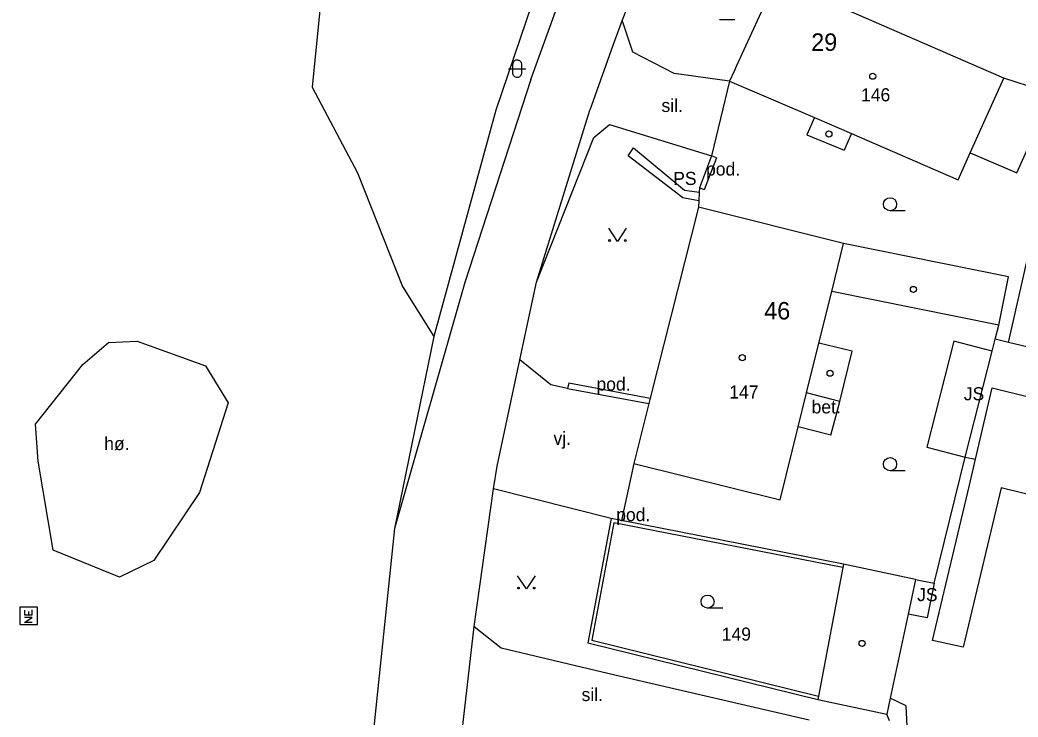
# Model space of a CAD drawing. Extents: x -836739 to -835945, y -1070775 to -1070126.
# Drawn here: x -836678.6 to -836621.5, y -1070479.9 to -1070440 of the extents above; entities that cross this region are included whole.
import ezdxf

# ---------------------------------------------------------------- set-up
doc = ezdxf.new("R2010")
doc.units = 0
for name, color, linetype in [('BodPole_mer', 7, 'Continuous'), ('Budovy_hranice', 7, 'Continuous'), ('Budovy_kody', 7, 'Continuous'), ('Doprava_hranice', 7, 'Continuous'), ('Doprava_kody', 7, 'Continuous'), ('OstPloch_hranice', 7, 'Continuous'), ('OstPloch_kody', 7, 'Continuous'), ('PovrZnIS_body', 7, 'Continuous'), ('RuianAdr_popis', 7, 'Continuous'), ('RuianPar_popis', 7, 'Continuous'), ('Stavby_hr_stav', 7, 'Continuous'), ('Stavby_kody', 7, 'Continuous'), ('Stavby_linie', 7, 'Continuous'), ('Zelen_kody', 7, 'Continuous')]:
    doc.layers.add(name, color=color, linetype=linetype)

msp = doc.modelspace()

# ---------------------------------------------------------------- linework, layer by layer
at = {"layer": 'BodPole_mer'}
for p, q in [((-836644.12, -1070440), (-836644.12, -1070440)), ((-836644.66, -1070441.44), (-836644.66, -1070441.44)), ((-836643.52, -1070441.83), (-836643.52, -1070441.83)), ((-836637.7, -1070442.88), (-836637.7, -1070442.88)), ((-836637.6, -1070442.65), (-836637.6, -1070442.65)), ((-836649.35, -1070443.39), (-836649.35, -1070443.39)), ((-836641.15, -1070443.05), (-836641.15, -1070443.05)), ((-836637.98, -1070443.48), (-836637.98, -1070443.48)), ((-836622.29, -1070443.32), (-836622.29, -1070443.32)), ((-836661.86, -1070443.82), (-836661.86, -1070443.82)), ((-836651.36, -1070445.15), (-836651.36, -1070445.15)), ((-836645.98, -1070445.15), (-836645.98, -1070445.15)), ((-836633.13, -1070445.57), (-836633.13, -1070445.57)), ((-836644.85, -1070445.96), (-836644.85, -1070445.96)), ((-836645.75, -1070446.71), (-836645.75, -1070446.71)), ((-836633.56, -1070446.56), (-836633.56, -1070446.56)), ((-836631.01, -1070446.49), (-836631.01, -1070446.49)), ((-836643.48, -1070447.3), (-836643.48, -1070447.3)), ((-836631.42, -1070447.44), (-836631.42, -1070447.44)), ((-836624.21, -1070447.58), (-836624.21, -1070447.58)), ((-836643.78, -1070447.76), (-836643.78, -1070447.76)), ((-836639.01, -1070447.76), (-836639.01, -1070447.76)), ((-836638.73, -1070447.87), (-836638.73, -1070447.87)), ((-836659.27, -1070448.73), (-836659.27, -1070448.73)), ((-836621.54, -1070448.73), (-836621.54, -1070448.73)), ((-836624.91, -1070449.13), (-836624.91, -1070449.13)), ((-836640.56, -1070449.72), (-836640.56, -1070449.72)), ((-836639.72, -1070449.85), (-836639.72, -1070449.85)), ((-836639.71, -1070449.6), (-836639.71, -1070449.6)), ((-836639.43, -1070449.71), (-836639.43, -1070449.71)), ((-836640.65, -1070450.17), (-836640.65, -1070450.17)), ((-836639.74, -1070450.33), (-836639.74, -1070450.33)), ((-836639.76, -1070450.7), (-836639.76, -1070450.7)), ((-836631.47, -1070452.78), (-836631.47, -1070452.78)), ((-836653.14, -1070455.02), (-836653.14, -1070455.02)), ((-836649.04, -1070455), (-836649.04, -1070455)), ((-836622.02, -1070454.69), (-836622.02, -1070454.69)), ((-836656.69, -1070455.24), (-836656.69, -1070455.24)), ((-836632.14, -1070455.52), (-836632.14, -1070455.52)), ((-836622.58, -1070457.45), (-836622.58, -1070457.45)), ((-836673.53, -1070458.44), (-836673.53, -1070458.44)), ((-836671.89, -1070458.38), (-836671.89, -1070458.38)), ((-836654.9, -1070458.11), (-836654.9, -1070458.11)), ((-836625.15, -1070458.38), (-836625.15, -1070458.38)), ((-836622.78, -1070458.25), (-836622.78, -1070458.25)), ((-836622.02, -1070458.45), (-836622.02, -1070458.45)), ((-836632.88, -1070458.48), (-836632.88, -1070458.48)), ((-836630.97, -1070458.95), (-836630.97, -1070458.95)), ((-836622.96, -1070458.94), (-836622.96, -1070458.94)), ((-836649.99, -1070459.44), (-836649.99, -1070459.44)), ((-836674.99, -1070459.71), (-836674.99, -1070459.71)), ((-836667.97, -1070459.78), (-836667.97, -1070459.78)), ((-836648.21, -1070460.88), (-836648.21, -1070460.88)), ((-836647.25, -1070461.08), (-836647.25, -1070461.08)), ((-836647.19, -1070460.76), (-836647.19, -1070460.76)), ((-836622.96, -1070461.05), (-836622.96, -1070461.05)), ((-836642.52, -1070461.63), (-836642.52, -1070461.63)), ((-836633.58, -1070461.34), (-836633.58, -1070461.34)), ((-836631.68, -1070461.82), (-836631.68, -1070461.82)), ((-836666.68, -1070461.9), (-836666.68, -1070461.9)), ((-836642.61, -1070461.95), (-836642.61, -1070461.95)), ((-836677.71, -1070463.13), (-836677.71, -1070463.13)), ((-836634.06, -1070463.28), (-836634.06, -1070463.28)), ((-836632.19, -1070463.75), (-836632.19, -1070463.75)), ((-836626.69, -1070464.45), (-836626.69, -1070464.45)), ((-836677.54, -1070465.24), (-836677.54, -1070465.24)), ((-836624.5, -1070465.01), (-836624.5, -1070465.01)), ((-836623.9, -1070465.13), (-836623.9, -1070465.13)), ((-836651.28, -1070465.53), (-836651.28, -1070465.53)), ((-836643.47, -1070465.37), (-836643.47, -1070465.37)), ((-836651.49, -1070466.82), (-836651.49, -1070466.82)), ((-836624.25, -1070466.62), (-836624.25, -1070466.62)), ((-836622.44, -1070466.77), (-836622.44, -1070466.77)), ((-836668.32, -1070467.04), (-836668.32, -1070467.04)), ((-836635.09, -1070467.46), (-836635.09, -1070467.46)), ((-836644.76, -1070468.53), (-836644.76, -1070468.53)), ((-836644.16, -1070468.65), (-836644.16, -1070468.65)), ((-836657.15, -1070469.1), (-836657.15, -1070469.1)), ((-836644.6, -1070468.77), (-836644.6, -1070468.77)), ((-836676.69, -1070470.34), (-836676.69, -1070470.34)), ((-836670.93, -1070470.93), (-836670.93, -1070470.93)), ((-836631.5, -1070471.34), (-836631.5, -1070471.34)), ((-836631.46, -1070471.15), (-836631.46, -1070471.15)), ((-836672.9, -1070471.89), (-836672.9, -1070471.89)), ((-836627.35, -1070472.02), (-836627.35, -1070472.02)), ((-836626.28, -1070472.23), (-836626.28, -1070472.23)), ((-836678.09, -1070474.1), (-836678.09, -1070474.1)), ((-836627.77, -1070474), (-836627.77, -1070474)), ((-836626.68, -1070474.21), (-836626.68, -1070474.21)), ((-836652.59, -1070474.71), (-836652.59, -1070474.71)), ((-836645.86, -1070475.49), (-836645.86, -1070475.49)), ((-836626.37, -1070475.52), (-836626.37, -1070475.52)), ((-836651.05, -1070475.93), (-836651.05, -1070475.93)), ((-836646.09, -1070475.64), (-836646.09, -1070475.64)), ((-836624.62, -1070475.89), (-836624.62, -1070475.89)), ((-836644.54, -1070477.48), (-836644.54, -1070477.48)), ((-836632.94, -1070478.89), (-836632.94, -1070478.89)), ((-836632.9, -1070478.69), (-836632.9, -1070478.69)), ((-836628.79, -1070478.81), (-836628.79, -1070478.81)), ((-836627.88, -1070479.26), (-836627.88, -1070479.26)), ((-836628.99, -1070479.73), (-836628.99, -1070479.73))]:
    msp.add_line(p, q, dxfattribs=at)
at = {"layer": 'Budovy_hranice'}
for p, q in [((-836622.29, -1070443.32), (-836635.32, -1070437.63)), ((-836616.07, -1070445.32), (-836622.29, -1070443.32)), ((-836633.13, -1070445.57), (-836633.56, -1070446.56)), ((-836633.56, -1070446.56), (-836631.42, -1070447.44)), ((-836631.01, -1070446.49), (-836631.42, -1070447.44)), ((-836621.54, -1070448.73), (-836620.62, -1070446.7)), ((-836624.21, -1070447.58), (-836621.54, -1070448.73)), ((-836622.58, -1070457.45), (-836622.02, -1070454.69)), ((-836622.58, -1070457.45), (-836632.14, -1070455.52)), ((-836630.97, -1070458.95), (-836632.88, -1070458.48)), ((-836631.68, -1070461.82), (-836630.97, -1070458.95)), ((-836631.68, -1070461.82), (-836633.58, -1070461.34)), ((-836643.47, -1070465.37), (-836635.09, -1070467.46)), ((-836627.35, -1070472.02), (-836631.46, -1070471.15)), ((-836632.94, -1070478.89), (-836628.99, -1070479.73))]:
    msp.add_line(p, q, dxfattribs=at)
for points in [[(-836635.32, -1070437.63), (-836635.42, -1070437.86), (-836637.6, -1070442.65), (-836637.7, -1070442.88), (-836637.98, -1070443.48)], [(-836637.98, -1070443.48), (-836633.13, -1070445.57), (-836631.01, -1070446.49), (-836624.91, -1070449.13)], [(-836624.91, -1070449.13), (-836624.21, -1070447.58), (-836622.29, -1070443.32)], [(-836616.17, -1070459.86), (-836616.95, -1070459.66), (-836622.02, -1070458.45), (-836620.76, -1070452.9), (-836617.02, -1070453.79), (-836616.09, -1070450.28), (-836613.73, -1070450.82)], [(-836639.76, -1070450.7), (-836642.52, -1070461.63), (-836642.61, -1070461.95), (-836643.47, -1070465.37)], [(-836622.02, -1070454.69), (-836631.47, -1070452.78), (-836639.76, -1070450.7)], [(-836635.09, -1070467.46), (-836634.06, -1070463.28), (-836633.58, -1070461.34), (-836632.88, -1070458.48), (-836632.14, -1070455.52), (-836631.47, -1070452.78)], [(-836631.46, -1070471.15), (-836631.5, -1070471.34), (-836632.9, -1070478.69), (-836632.94, -1070478.89)], [(-836627.35, -1070472.02), (-836627.77, -1070474), (-836628.79, -1070478.81), (-836628.99, -1070479.73)]]:
    msp.add_lwpolyline(points, dxfattribs=at)
at = {"layer": 'Budovy_kody'}
for centre in [(-836629.79, -1070443.2), (-836632.3, -1070446.51), (-836627.46, -1070455.41), (-836637.26, -1070459.32), (-836632.23, -1070460.21), (-836630.4, -1070475.68)]:
    msp.add_circle(centre, 0.175, dxfattribs=at)
at = {"layer": 'Doprava_hranice'}
for p, q in [((-836649.35, -1070443.39), (-836653.14, -1070455.02)), ((-836649.04, -1070455), (-836645.98, -1070445.15)), ((-836653.14, -1070455.02), (-836657.15, -1070469.1)), ((-836644.76, -1070468.53), (-836651.49, -1070466.82)), ((-836657.15, -1070469.1), (-836658.42, -1070481.32)), ((-836653.53, -1070482.71), (-836652.59, -1070474.71)), ((-836652.59, -1070474.71), (-836651.05, -1070475.93)), ((-836651.05, -1070475.93), (-836644.54, -1070477.48)), ((-836644.54, -1070477.48), (-836633.42, -1070480.06)), ((-836628.84, -1070480.11), (-836628.99, -1070479.73))]:
    msp.add_line(p, q, dxfattribs=at)
for points in [[(-836629.46, -1070381.04), (-836630.1, -1070382.38), (-836632.83, -1070381.55), (-836636.09, -1070386.19), (-836641.48, -1070386.97), (-836650.79, -1070382.45), (-836653.8, -1070405.82), (-836653.8, -1070413.64), (-836660.69, -1070431.93), (-836661.86, -1070443.82), (-836659.27, -1070448.73), (-836656.69, -1070455.24), (-836654.9, -1070458.11)], [(-836626.49, -1070382.25), (-836628.93, -1070385.76), (-836634.87, -1070398.93), (-836637.79, -1070403.09), (-836640.55, -1070405.67), (-836641.83, -1070408.47), (-836641.31, -1070415.5), (-836651.36, -1070445.15), (-836654.9, -1070458.11), (-836657.15, -1070469.1)], [(-836649.35, -1070443.39), (-836643.96, -1070428.49), (-836637.13, -1070410.36)], [(-836636.57, -1070420.39), (-836639.98, -1070429.29), (-836642.32, -1070435.38), (-836644.12, -1070440), (-836644.66, -1070441.44), (-836645.98, -1070445.15)], [(-836637.98, -1070443.48), (-836641.15, -1070443.05), (-836643.52, -1070441.83), (-836644.12, -1070440)], [(-836649.04, -1070455), (-836645.75, -1070446.71), (-836644.85, -1070445.96), (-836639.01, -1070447.76)], [(-836651.28, -1070465.53), (-836649.99, -1070459.44), (-836649.04, -1070455)], [(-836647.25, -1070461.08), (-836648.21, -1070460.88), (-836649.99, -1070459.44)], [(-836652.59, -1070474.71), (-836651.49, -1070466.82), (-836651.28, -1070465.53)]]:
    msp.add_lwpolyline(points, dxfattribs=at)
at = {"layer": 'OstPloch_hranice'}
msp.add_line((-836624.5, -1070465.01), (-836623.9, -1070465.13), dxfattribs=at)
msp.add_lwpolyline([(-836670.93, -1070470.93), (-836672.9, -1070471.89), (-836676.69, -1070470.34), (-836677.54, -1070465.24), (-836677.71, -1070463.13), (-836674.99, -1070459.71), (-836673.53, -1070458.44), (-836671.89, -1070458.38), (-836667.97, -1070459.78), (-836666.68, -1070461.9), (-836668.32, -1070467.04), (-836670.93, -1070470.93)], dxfattribs=at)
at = {"layer": 'OstPloch_kody'}
for p, q in [((-836637.675, -1070439.98), (-836638.55, -1070439.98)), ((-836650.64, -1070442.77), (-836649.64, -1070442.77)), ((-836650.39, -1070443.02), (-836650.39, -1070442.52)), ((-836649.89, -1070442.52), (-836649.89, -1070443.02)), ((-836627.925, -1070450.91), (-836628.8, -1070450.91)), ((-836627.925, -1070465.79), (-836628.8, -1070465.79)), ((-836638.365, -1070473.66), (-836639.24, -1070473.66))]:
    msp.add_line(p, q, dxfattribs=at)
for points in [[(-836650.14, -1070442.27), (-836650.185, -1070442.274), (-836650.232, -1070442.288), (-836650.277, -1070442.311), (-836650.317, -1070442.343), (-836650.349, -1070442.383), (-836650.372, -1070442.428), (-836650.386, -1070442.475), (-836650.39, -1070442.52)], [(-836650.14, -1070442.27), (-836650.095, -1070442.274), (-836650.048, -1070442.288), (-836650.003, -1070442.311), (-836649.963, -1070442.343), (-836649.931, -1070442.383), (-836649.908, -1070442.428), (-836649.894, -1070442.475), (-836649.89, -1070442.52)], [(-836650.14, -1070443.27), (-836650.185, -1070443.266), (-836650.232, -1070443.252), (-836650.277, -1070443.229), (-836650.317, -1070443.197), (-836650.349, -1070443.157), (-836650.372, -1070443.112), (-836650.386, -1070443.065), (-836650.39, -1070443.02)], [(-836649.89, -1070443.02), (-836649.894, -1070443.065), (-836649.908, -1070443.112), (-836649.931, -1070443.157), (-836649.963, -1070443.197), (-836650.003, -1070443.229), (-836650.048, -1070443.252), (-836650.095, -1070443.266), (-836650.14, -1070443.27)]]:
    msp.add_lwpolyline(points, dxfattribs=at)
for centre in [(-836628.8, -1070450.535), (-836628.8, -1070465.415), (-836639.24, -1070473.285)]:
    msp.add_ellipse(centre, major_axis=(0.375, 0), ratio=0.999999, dxfattribs=at)
at = {"layer": 'PovrZnIS_body'}
for p, q in [((-836677.59, -1070473.6), (-836678.59, -1070473.6)), ((-836678.59, -1070473.6), (-836678.59, -1070474.6)), ((-836677.59, -1070474.6), (-836677.59, -1070473.6)), ((-836678.59, -1070474.6), (-836677.59, -1070474.6))]:
    msp.add_line(p, q, dxfattribs=at)
for points in [[(-836678.333, -1070473.772), (-836678.333, -1070474.035)], [(-836678.108, -1070473.848), (-836678.108, -1070474.035)], [(-836677.883, -1070474.035), (-836677.883, -1070473.754)], [(-836678.333, -1070474.035), (-836677.883, -1070474.035)], [(-836678.333, -1070474.485), (-836677.883, -1070474.201)], [(-836677.883, -1070474.201), (-836678.333, -1070474.201)], [(-836677.883, -1070474.485), (-836678.333, -1070474.485)]]:
    msp.add_lwpolyline(points, dxfattribs=at)
at = {"layer": 'RuianAdr_popis'}
for p, q in [((-836633.31, -1070441.75), (-836633.31, -1070441.75)), ((-836636, -1070457.13), (-836636, -1070457.13))]:
    msp.add_line(p, q, dxfattribs=at)
at = {"layer": 'RuianPar_popis'}
for p, q in [((-836630.46, -1070444.64), (-836630.46, -1070444.64)), ((-836638, -1070461.66), (-836638, -1070461.66)), ((-836638.43, -1070475.52), (-836638.43, -1070475.52))]:
    msp.add_line(p, q, dxfattribs=at)
at = {"layer": 'Stavby_hr_stav'}
for p, q in [((-836639.01, -1070447.76), (-836639.71, -1070449.6)), ((-836638.73, -1070447.87), (-836639.01, -1070447.76)), ((-836639.43, -1070449.71), (-836639.71, -1070449.6)), ((-836647.19, -1070460.76), (-836647.25, -1070461.08)), ((-836647.25, -1070461.08), (-836642.61, -1070461.95)), ((-836632.19, -1070463.75), (-836631.68, -1070461.82)), ((-836632.19, -1070463.75), (-836634.06, -1070463.28))]:
    msp.add_line(p, q, dxfattribs=at)
for points in [[(-836639.74, -1070450.33), (-836640.65, -1070450.17), (-836643.78, -1070447.76), (-836643.48, -1070447.3), (-836640.56, -1070449.72), (-836639.72, -1070449.85)], [(-836626.69, -1070464.45), (-836624.5, -1070465.01), (-836622.96, -1070458.94), (-836625.15, -1070458.38), (-836626.69, -1070464.45)], [(-836626.37, -1070475.52), (-836624.25, -1070466.62), (-836623.9, -1070465.13), (-836622.96, -1070461.05), (-836614.56, -1070463.12), (-836605.88, -1070465.16), (-836606.31, -1070466.85), (-836607.22, -1070470.35), (-836616.08, -1070468.33), (-836622.44, -1070466.77), (-836624.62, -1070475.89), (-836626.37, -1070475.52)], [(-836631.46, -1070471.15), (-836644.16, -1070468.65), (-836644.76, -1070468.53), (-836646.09, -1070475.64), (-836632.94, -1070478.89)], [(-836627.35, -1070472.02), (-836626.28, -1070472.23), (-836626.68, -1070474.21), (-836627.77, -1070474)]]:
    msp.add_lwpolyline(points, dxfattribs=at)
at = {"layer": 'Stavby_linie'}
for p, q in [((-836637.98, -1070443.48), (-836639.01, -1070447.76)), ((-836638.73, -1070447.87), (-836639.43, -1070449.71)), ((-836622.02, -1070458.45), (-836622.78, -1070458.25)), ((-836647.19, -1070460.76), (-836642.52, -1070461.63)), ((-836626.28, -1070472.23), (-836624.5, -1070465.01)), ((-836643.47, -1070465.37), (-836644.16, -1070468.65))]:
    msp.add_line(p, q, dxfattribs=at)
for points in [[(-836639.71, -1070449.6), (-836639.72, -1070449.85), (-836639.74, -1070450.33), (-836639.76, -1070450.7)], [(-836622.96, -1070458.94), (-836622.78, -1070458.25), (-836622.58, -1070457.45)], [(-836631.5, -1070471.34), (-836644.6, -1070468.77), (-836645.86, -1070475.49), (-836632.9, -1070478.69)], [(-836627.77, -1070484.71), (-836627.64, -1070483.88), (-836627.88, -1070479.26), (-836628.79, -1070478.81)]]:
    msp.add_lwpolyline(points, dxfattribs=at)
at = {"layer": 'Zelen_kody'}
for points in [[(-836643.9, -1070451.91), (-836644.4, -1070452.66), (-836644.9, -1070451.91)], [(-836649.11, -1070471.81), (-836649.61, -1070472.56), (-836650.11, -1070471.81)]]:
    msp.add_lwpolyline(points, dxfattribs=at)
for centre in [(-836644.849, -1070452.61), (-836643.949, -1070452.61), (-836650.059, -1070472.51), (-836649.159, -1070472.51)]:
    msp.add_circle(centre, 0.05, dxfattribs=at)

# ---------------------------------------------------------------- texts
at = {"layer": 'Doprava_kody'}
for s, p in [('sil.', (-836641.88, -1070445.25)), ('vj.', (-836648.06, -1070464.31)), ('sil.', (-836646.45, -1070478.98))]:
    msp.add_text(s, height=0.75, dxfattribs=at).set_placement(p)
at = {"layer": 'OstPloch_kody'}
msp.add_text('hø.', height=0.75, dxfattribs=at).set_placement((-836673.77, -1070464.61))
at = {"layer": 'RuianAdr_popis'}
for s, p in [('29', (-836633.31, -1070441.75)), ('46', (-836636, -1070457.13))]:
    msp.add_text(s, height=1, dxfattribs=at).set_placement(p)
at = {"layer": 'RuianPar_popis'}
for s, p in [('146', (-836630.46, -1070444.64)), ('147', (-836638, -1070461.66)), ('149', (-836638.43, -1070475.52))]:
    msp.add_text(s, height=0.75, dxfattribs=at).set_placement(p)
at = {"layer": 'Stavby_kody'}
for s, p in [('pod.', (-836639.33, -1070448.89)), ('PS', (-836641.21, -1070449.43)), ('pod.', (-836645.6, -1070461.2)), ('JS', (-836624.58, -1070461.76)), ('bet.', (-836633.29, -1070462.51)), ('pod.', (-836644.47, -1070468.68)), ('JS', (-836627.25, -1070473.26))]:
    msp.add_text(s, height=0.75, dxfattribs=at).set_placement(p)

doc.saveas('drawing.dxf')
